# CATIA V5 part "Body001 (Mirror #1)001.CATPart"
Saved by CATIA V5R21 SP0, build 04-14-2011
Part number: Body001 (Mirror #1)001
Definition: design
Nomenclature: Body001 (Mirror #1)001
Source: Unknown
Bounding box of the stored display mesh (mm): x -0.8 to -0.6, y -0.4 to 0.4, z 0 to 1
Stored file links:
  C:\Users\beatr\OneDrive\Documents\UNB\2026_1\Pi1\Componentes eletronicos\Encoder\Body001 (Mirror #1)001.CATPart
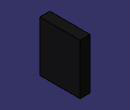
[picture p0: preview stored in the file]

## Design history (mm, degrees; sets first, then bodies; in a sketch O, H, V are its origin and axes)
Body1 "MANIFOLD_SOLID_BREP #4658" (main body)
  Solid1: solid without history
